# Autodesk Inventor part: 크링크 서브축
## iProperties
Manager: KYOUNG IL JANG
Company: 한국ATC센터
Created: 2012-10
Part Number: 크링크 서브축
Document SubType Name: Modeling
Density: 1 g/cm^3
Checked By: KYOUNG IL JANG
Vendor: CBT Solutions
Designer: KYOUNG IL JANG
Author: KYOUNG IL JANG
